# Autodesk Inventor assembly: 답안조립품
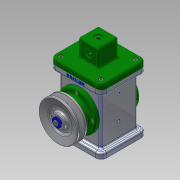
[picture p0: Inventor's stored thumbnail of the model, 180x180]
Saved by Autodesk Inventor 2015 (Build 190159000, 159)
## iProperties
Created: 2017-08
Part Number: 답안조립품
Document SubType Name: Assembly
Designer: Administrator
Author: Administrator
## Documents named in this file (18)
- C:\Users\Administrator\Desktop\470807V1016\답안조립품.iam
- C:\Users\Administrator\Desktop\470807V1016\본체.ipt
- C:\Users\Administrator\Desktop\470807V1016\E-링.ipt
- C:\Users\Administrator\Desktop\470807V1016\V-벨트풀리.ipt
- C:\Users\Administrator\Desktop\470807V1016\덮개.ipt
- C:\Users\Administrator\Desktop\470807V1016\뒤커버.ipt
- C:\Users\Administrator\Desktop\470807V1016\링크.ipt
- C:\Users\Administrator\Desktop\470807V1016\베어링 17 x 40 x 12.ipt
- C:\Users\Administrator\Desktop\470807V1016\볼트 M4 x 8.ipt
- C:\Users\Administrator\Desktop\470807V1016\볼트 M4 x 10.ipt
- C:\Users\Administrator\Desktop\470807V1016\슬라이더.ipt
- C:\Users\Administrator\Desktop\470807V1016\앞커버.ipt
- C:\Users\Administrator\Desktop\470807V1016\오일 실 17 30 8.ipt
- C:\Users\Administrator\Desktop\470807V1016\와셔 4x16.ipt
- C:\Users\Administrator\Desktop\470807V1016\클레비스 핀 6 x 22.ipt
- 클레비스 핀 6 x 22.ipt
- C:\Users\Administrator\Desktop\470807V1016\키 4 x 4 x 12.ipt
- C:\Users\Administrator\Desktop\470807V1016\편심축.ipt
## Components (2 placed, 2 different names)
1. E-링:1 — 각도:2
2. V-벨트풀리:1 — 각도:3
## Component patterns: 구성요소 패턴 3:2 (2 elements)
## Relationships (2: Angle 2)
- 각도:2 [Angle]: E-링:1
- 각도:3 [Angle]: V-벨트풀리:1
